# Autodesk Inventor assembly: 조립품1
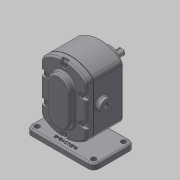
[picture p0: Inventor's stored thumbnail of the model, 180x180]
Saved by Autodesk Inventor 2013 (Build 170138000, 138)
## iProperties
Created: 2019-03
Part Number: 조립품1
Document SubType Name: Assembly
Designer: Administrator
Author: Administrator
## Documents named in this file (11)
- C:\Users\Administrator\Desktop\490307V1039\조립품1.iam
- C:\Users\Administrator\Desktop\490307V1039\본체.ipt
- C:\Users\Administrator\Desktop\490307V1039\메인축.ipt
- C:\Users\Administrator\Desktop\490307V1039\키 6 x 6 x 18.ipt
- C:\Users\Administrator\Desktop\490307V1039\스퍼기어.ipt
- C:\Users\Administrator\Desktop\490307V1039\베어링부시.ipt
- C:\Users\Administrator\Desktop\490307V1039\서브축.ipt
- C:\Users\Administrator\Desktop\490307V1039\개스킷.ipt
- C:\Users\Administrator\Desktop\490307V1039\커버.ipt
- C:\Users\Administrator\Desktop\490307V1039\볼트 M5.ipt
- C:\Users\Administrator\Desktop\490307V1039\오일 실 16 28 7.ipt
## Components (1 placed, 1 different names)
1. 개스킷:1
